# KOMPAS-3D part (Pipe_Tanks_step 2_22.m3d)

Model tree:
1. X Axis
2. Y Axis
3. Z Axis  (labels: Pipe Dn 50; T-Bend Dn 50)
     Òîëùèíà ñòåíêè 1 = 1

Referenced files in C:\Documents and Settings\kashirsky\Мои документы\Camtasia Studio\Pipelines3D\Tanks\: Tanks_step 2.a3d
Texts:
  Pipe Dn 50
  Steel ASTM A295
  Three Point Plane
  Plane at Angle
  Line and Point Plane
  Axis through Two Vertices
  Axis of Feature
  Axis of Conical Surface
  Axis through Edge
  Trim by Surface
  Trim by Sketch
  Feature with No History
  Intersection Axis of Two Planes
  Two Line Plane
  Line and Face Plane
  Bend by line
  Hole in sheet body
  Cut in sheet body
  Point in CM
  Linear Dimension from Line to Point
  Surface Finish Symbol
  Geometric Tolerance Symbol
  Leader #1
  Leader #2
  Leader #3
  Shape Deviations and Datum
  Node point number
  Mark of coordination axis
  Node point designation
  Mark/Reference designation with leader
  Mark/reference designation on line
  Mark/Reference designation without leader
  T-Bend Dn 50
  Plane of section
